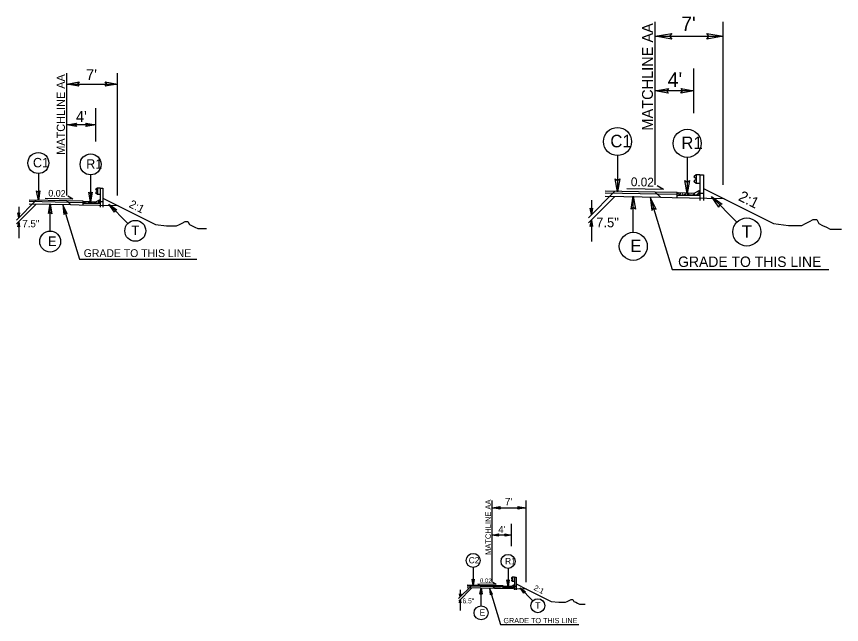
# Model space of a CAD drawing. Extents: x 1818040 to 1825768, y 638918 to 648046.
# Drawn here: x 1818040 to 1819741, y 646793 to 648046 of the extents above; entities that cross this region are included whole.
import ezdxf

# ---------------------------------------------------------------- set-up
doc = ezdxf.new("R2010")
doc.units = 0
for name, color, linetype in [('Old_Level_1', 7, 'Continuous'), ('Prop Dimension', 7, 'Continuous'), ('Prop Dimension Text', 7, 'Continuous'), ('Typical Curb CELL', 7, 'Continuous'), ('Typical Guardrail CELL', 7, 'Continuous'), ('Typical ID Circle CELL', 7, 'Continuous'), ('Typical Pavement Slope CELL', 7, 'Continuous'), ('Typical Pavement Slope Information CELL', 7, 'Continuous'), ('Typical Slope Point Local CELL', 7, 'Continuous'), ('Typical Terminator CELL', 7, 'Continuous'), ('Typical Text General CELL', 7, 'Continuous'), ('Typical Text ID Circle CELL', 7, 'Continuous'), ('Typical Text Label CELL', 7, 'Continuous')]:
    doc.layers.add(name, color=color, linetype=linetype)

msp = doc.modelspace()

# ---------------------------------------------------------------- linework, layer by layer
at = {"layer": 'Old_Level_1'}
for p, q in [((1819273.4, 647685.8), (1819218.9, 647631.3)), ((1819356.8, 647684.1), (1819367.9, 647673)), ((1819447.1, 647687.1), (1819448.8, 647687.9)), ((1818080.9, 647667.2), (1818040.1, 647626.4)), ((1818211.2, 647668.2), (1818212.5, 647668.8)), ((1819273.4, 647674.9), (1819219.2, 647620.8)), ((1819225.1, 647667.3), (1819225.1, 647637.6)), ((1819367.9, 647673), (1819253.6, 647675.3)), ((1819361.1, 647679.8), (1819253.7, 647682)), ((1819346.3, 647673.5), (1819391.8, 647524.4)), ((1819401.8, 647679), (1819361.1, 647679.8)), ((1819391.5, 647672.6), (1819367.9, 647673)), ((1819498.7, 647670.4), (1819391.5, 647672.6)), ((1819401.8, 647672.4), (1819401.8, 647676.9)), ((1818080.9, 647659.1), (1818040.3, 647618.5)), ((1818044.7, 647653.4), (1818044.7, 647631.1)), ((1818151.8, 647657.7), (1818066.1, 647659.4)), ((1818146.7, 647662.8), (1818066.2, 647664.4)), ((1818135.6, 647658), (1818169.8, 647546.2)), ((1818143.5, 647666), (1818151.8, 647657.7)), ((1818177.3, 647662.2), (1818146.7, 647662.8)), ((1818169.5, 647657.3), (1818151.8, 647657.7)), ((1818249.9, 647655.7), (1818169.5, 647657.3)), ((1818177.3, 647657.2), (1818177.3, 647660.6)), ((1818044.7, 647622.9), (1818044.7, 647589.4)), ((1819225.1, 647626.6), (1819225.1, 647582)), ((1818169.8, 647546.2), (1818411.6, 647546.2)), ((1819391.8, 647524.4), (1819714.3, 647524.4)), ((1818978.6, 646874.1), (1818951.4, 646846.9)), ((1818978.6, 646868.7), (1818951.6, 646841.7)), ((1819025.9, 646867.8), (1818968.7, 646868.9)), ((1819022.5, 646871.2), (1818968.8, 646872.3)), ((1819015.1, 646868), (1819037.9, 646793.5)), ((1819020.4, 646873.3), (1819025.9, 646867.8)), ((1819042.9, 646870.8), (1819022.5, 646871.2)), ((1819037.7, 646867.5), (1819025.9, 646867.8)), ((1819091.3, 646866.5), (1819037.7, 646867.5)), ((1819042.9, 646867.4), (1819042.9, 646869.7)), ((1819065.5, 646874.8), (1819066.3, 646875.2)), ((1818954.5, 646864.9), (1818954.5, 646850.1)), ((1818954.5, 646844.6), (1818954.5, 646822.3)), ((1819037.9, 646793.5), (1819199.1, 646793.5))]:
    msp.add_line(p, q, dxfattribs=at)
at = {"layer": 'Prop Dimension'}
for p, q in [((1819356.8, 647699), (1819356.8, 648035)), ((1819496.8, 647699), (1819496.8, 648035)), ((1819356.8, 648005), (1819496.8, 648005)), ((1819436.5, 647847), (1819436.5, 647938.6)), ((1818143.5, 647677.2), (1818143.5, 647929.1)), ((1818248.5, 647677.2), (1818248.5, 647929.1)), ((1818143.5, 647906.6), (1818248.5, 647906.6)), ((1819436.5, 647892.8), (1819356.8, 647892.8)), ((1818203.3, 647788.1), (1818203.3, 647856.9)), ((1818203.3, 647822.5), (1818143.5, 647822.5)), ((1819020.4, 646880.8), (1819020.4, 647048.8)), ((1819090.4, 646880.8), (1819090.4, 647048.8)), ((1819020.4, 647033.8), (1819090.4, 647033.8)), ((1819060.2, 646954.8), (1819060.2, 647000.6)), ((1819060.2, 646977.7), (1819020.4, 646977.7))]:
    msp.add_line(p, q, dxfattribs=at)
at = {"layer": 'Typical Curb CELL'}
for p, q in [((1819401.8, 647683.2), (1819401.8, 647683.2)), ((1819401.8, 647676.9), (1819401.8, 647683)), ((1819402, 647683.2), (1819436.8, 647681.9)), ((1819436.8, 647681.9), (1819447.1, 647687.1)), ((1819447.1, 647676.9), (1819447.1, 647687.1)), ((1818203.5, 647664.3), (1818211.2, 647668.2)), ((1818211.2, 647660.6), (1818211.2, 647668.2)), ((1819447.1, 647676.9), (1819401.8, 647676.9)), ((1819405.4, 647679.2), (1819406.7, 647681)), ((1819407.2, 647679.3), (1819405.4, 647679.2)), ((1819406.7, 647681), (1819407.2, 647679.3)), ((1819416.9, 647678.5), (1819417.8, 647680.2)), ((1819419.3, 647679), (1819416.9, 647678.5)), ((1819417.8, 647680.2), (1819419.3, 647679)), ((1819424.1, 647679.2), (1819425.4, 647681)), ((1819425.9, 647679.3), (1819424.1, 647679.2)), ((1819425.4, 647681), (1819425.9, 647679.3)), ((1819435.6, 647678.5), (1819436.5, 647680.2)), ((1819438.1, 647679), (1819435.6, 647678.5)), ((1819436.5, 647680.2), (1819438.1, 647679)), ((1819444.3, 647682.1), (1819444.5, 647680.7)), ((1819446.6, 647681.4), (1819444.3, 647682.1)), ((1819444.5, 647680.7), (1819446.6, 647681.4)), ((1818177.3, 647665.3), (1818177.3, 647665.3)), ((1818177.3, 647660.6), (1818177.3, 647665.2)), ((1818211.2, 647660.6), (1818177.3, 647660.6)), ((1818177.4, 647665.3), (1818203.5, 647664.3)), ((1818179.9, 647662.3), (1818180.9, 647663.7)), ((1818181.3, 647662.4), (1818179.9, 647662.3)), ((1818180.9, 647663.7), (1818181.3, 647662.4)), ((1818188.5, 647661.7), (1818189.2, 647663)), ((1818190.4, 647662.2), (1818188.5, 647661.7)), ((1818189.2, 647663), (1818190.4, 647662.2)), ((1818194, 647662.3), (1818194.9, 647663.7)), ((1818195.3, 647662.4), (1818194, 647662.3)), ((1818194.9, 647663.7), (1818195.3, 647662.4)), ((1818202.6, 647661.7), (1818203.3, 647663)), ((1818204.4, 647662.2), (1818202.6, 647661.7)), ((1818203.3, 647663), (1818204.4, 647662.2)), ((1818209.1, 647664.5), (1818209.3, 647663.4)), ((1818210.8, 647664), (1818209.1, 647664.5)), ((1818209.3, 647663.4), (1818210.8, 647664)), ((1819042.9, 646872.9), (1819060.4, 646872.2)), ((1819042.9, 646872.9), (1819042.9, 646872.9)), ((1819042.9, 646869.7), (1819042.9, 646872.8)), ((1819065.5, 646869.7), (1819042.9, 646869.7)), ((1819044.6, 646870.9), (1819045.3, 646871.8)), ((1819045.5, 646870.9), (1819044.6, 646870.9)), ((1819045.3, 646871.8), (1819045.5, 646870.9)), ((1819050.4, 646870.5), (1819050.8, 646871.4)), ((1819051.6, 646870.8), (1819050.4, 646870.5)), ((1819050.8, 646871.4), (1819051.6, 646870.8)), ((1819054, 646870.9), (1819054.6, 646871.8)), ((1819054.9, 646870.9), (1819054, 646870.9)), ((1819054.6, 646871.8), (1819054.9, 646870.9)), ((1819059.7, 646870.5), (1819060.2, 646871.4)), ((1819061, 646870.8), (1819059.7, 646870.5)), ((1819060.2, 646871.4), (1819061, 646870.8)), ((1819060.4, 646872.2), (1819065.5, 646874.8)), ((1819064.1, 646872.3), (1819064.2, 646871.6)), ((1819065.2, 646872), (1819064.1, 646872.3)), ((1819064.2, 646871.6), (1819065.2, 646872)), ((1819065.5, 646869.7), (1819065.5, 646874.8))]:
    msp.add_line(p, q, dxfattribs=at)
for centre, radius in [((1819403.2, 647680.5), 0.12), ((1819403.7, 647682.4), 0.12), ((1819409.2, 647681.3), 0.12), ((1819410.1, 647678.6), 0.12), ((1819411, 647678.1), 0.12), ((1819411.5, 647680), 0.12), ((1819412.6, 647680), 0.12), ((1819413.4, 647680.4), 0.12), ((1819414.1, 647678.7), 0.12), ((1819417, 647679.3), 0.12), ((1819420.1, 647679), 0.12), ((1819420.3, 647679.8), 0.12), ((1819420.5, 647680.7), 0.12), ((1819421.3, 647678.5), 0.12), ((1819422.8, 647679.2), 0.12), ((1819424.2, 647679.4), 0.12), ((1819426, 647678.6), 0.12), ((1819428.9, 647678.6), 0.12), ((1819429.7, 647678.1), 0.12), ((1819430.2, 647680), 0.12), ((1819432.1, 647680.4), 0.12), ((1819432.8, 647678.7), 0.12), ((1819435.7, 647679.3), 0.12), ((1819436.1, 647677.8), 0.12), ((1819438.8, 647679), 0.12), ((1819439, 647679.8), 0.12), ((1819442.9, 647679.4), 0.12), ((1819444.7, 647678.6), 0.12), ((1819446.2, 647682.7), 0.12), ((1818178.3, 647663.3), 0.0902), ((1818178.7, 647664.7), 0.0902), ((1818182.8, 647663.9), 0.0902), ((1818183.5, 647661.8), 0.0902), ((1818184.1, 647661.5), 0.0902), ((1818184.5, 647662.9), 0.0902), ((1818185.3, 647662.9), 0.0902), ((1818185.9, 647663.2), 0.0902), ((1818186.4, 647661.9), 0.0902), ((1818188.6, 647662.3), 0.0902), ((1818190.9, 647662.2), 0.0902), ((1818191.1, 647662.7), 0.0902), ((1818191.2, 647663.4), 0.0902), ((1818191.9, 647661.8), 0.0902), ((1818193, 647662.3), 0.0902), ((1818194, 647662.4), 0.0902), ((1818195.4, 647661.8), 0.0902), ((1818197.5, 647661.8), 0.0902), ((1818198.2, 647661.5), 0.0902), ((1818198.5, 647662.9), 0.0902), ((1818200, 647663.2), 0.0902), ((1818200.5, 647661.9), 0.0902), ((1818202.7, 647662.3), 0.0902), ((1818203, 647661.2), 0.0902), ((1818205, 647662.2), 0.0902), ((1818205.2, 647662.7), 0.0902), ((1818208.1, 647662.4), 0.0902), ((1818209.4, 647661.8), 0.0902), ((1818210.5, 647664.9), 0.0902), ((1819043.5, 646871.5), 0.0602), ((1819043.8, 646872.5), 0.0602), ((1819046.6, 646871.9), 0.0602), ((1819047, 646870.6), 0.0602), ((1819047.4, 646870.3), 0.0602), ((1819047.7, 646871.3), 0.0602), ((1819048.2, 646871.3), 0.0602), ((1819048.6, 646871.5), 0.0602), ((1819049, 646870.6), 0.0602), ((1819050.4, 646870.9), 0.0602), ((1819052, 646870.8), 0.0602), ((1819052.1, 646871.2), 0.0602), ((1819052.2, 646871.6), 0.0602), ((1819052.6, 646870.5), 0.0602), ((1819053.3, 646870.9), 0.0602), ((1819054, 646871), 0.0602), ((1819054.9, 646870.6), 0.0602), ((1819056.4, 646870.6), 0.0602), ((1819056.8, 646870.3), 0.0602), ((1819057, 646871.3), 0.0602), ((1819058, 646871.5), 0.0602), ((1819058.3, 646870.6), 0.0602), ((1819059.8, 646870.9), 0.0602), ((1819060, 646870.1), 0.0602), ((1819061.3, 646870.8), 0.0602), ((1819061.5, 646871.2), 0.0602), ((1819063.4, 646871), 0.0602), ((1819064.3, 646870.6), 0.0602), ((1819065, 646872.6), 0.0602)]:
    msp.add_circle(centre, radius, dxfattribs=at)
for centre, radius in [((1819402, 647683), 0.156), ((1818177.4, 647665.2), 0.117), ((1819042.9, 646872.8), 0.0781)]:
    msp.add_arc(centre, radius, 87.952, 180, dxfattribs=at)
at = {"layer": 'Typical Guardrail CELL'}
for p, q in [((1819441.3, 647719.4), (1819437, 647716.4)), ((1819448.8, 647719.4), (1819441.3, 647719.4)), ((1819441.3, 647719.4), (1819441.3, 647702)), ((1819448.8, 647719.4), (1819448.8, 647682.1)), ((1819448.8, 647719.4), (1819456.2, 647719.4)), ((1819456.2, 647719.4), (1819456.2, 647682.1)), ((1819441.3, 647711.4), (1819437, 647714.5)), ((1819441.3, 647710), (1819437, 647707)), ((1819441.3, 647702), (1819437, 647705.1)), ((1819441.3, 647710.7), (1819441.3, 647711.4)), ((1819441.3, 647710.7), (1819441.3, 647710)), ((1819448.8, 647702), (1819441.3, 647702)), ((1818206.9, 647692.5), (1818203.6, 647690.2)), ((1818206.9, 647686.5), (1818203.6, 647688.7)), ((1818206.9, 647685.4), (1818203.6, 647683.1)), ((1818212.5, 647692.5), (1818206.9, 647692.5)), ((1818206.9, 647692.5), (1818206.9, 647679.4)), ((1818206.9, 647685.9), (1818206.9, 647686.5)), ((1818206.9, 647685.9), (1818206.9, 647685.4)), ((1818212.5, 647692.5), (1818212.5, 647664.5)), ((1818212.5, 647692.5), (1818218.1, 647692.5)), ((1818218.1, 647692.5), (1818218.1, 647664.5)), ((1818206.9, 647679.4), (1818203.6, 647681.7)), ((1818212.5, 647679.4), (1818206.9, 647679.4)), ((1819448.8, 647682.1), (1819456.2, 647682.1)), ((1819448.8, 647682.1), (1819448.8, 647667)), ((1819456.2, 647682.1), (1819456.2, 647667)), ((1818212.5, 647664.5), (1818218.1, 647664.5)), ((1818212.5, 647664.5), (1818212.5, 647653.1)), ((1818218.1, 647664.5), (1818218.1, 647653.1)), ((1819062.6, 646891), (1819060.4, 646889.5)), ((1819062.6, 646887), (1819060.4, 646888.5)), ((1819062.6, 646886.3), (1819060.4, 646884.8)), ((1819062.6, 646882.3), (1819060.4, 646883.8)), ((1819066.3, 646891), (1819062.6, 646891)), ((1819062.6, 646891), (1819062.6, 646882.3)), ((1819062.6, 646886.6), (1819062.6, 646887)), ((1819062.6, 646886.6), (1819062.6, 646886.3)), ((1819066.3, 646891), (1819066.3, 646872.3)), ((1819066.3, 646891), (1819070.1, 646891)), ((1819070.1, 646891), (1819070.1, 646872.3)), ((1819066.3, 646882.3), (1819062.6, 646882.3)), ((1819066.3, 646872.3), (1819070.1, 646872.3)), ((1819066.3, 646872.3), (1819066.3, 646864.8)), ((1819070.1, 646872.3), (1819070.1, 646864.8))]:
    msp.add_line(p, q, dxfattribs=at)
for centre, radius, start, end in [((1819437.7, 647715.4), 1.16, 125.003, 235.0112), ((1819437.7, 647706), 1.16, 125.0059, 235.0366), ((1818204.1, 647689.5), 0.874, 125.003, 235.0112), ((1818204.1, 647682.4), 0.874, 125.0059, 235.0366), ((1819060.8, 646889), 0.582, 125.003, 235.0112), ((1819060.8, 646884.3), 0.582, 125.0059, 235.0366)]:
    msp.add_arc(centre, radius, start, end, dxfattribs=at)
at = {"layer": 'Typical ID Circle CELL'}
for p, q in [((1819278.9, 647759.4), (1819278.9, 647684.8)), ((1819422.6, 647755.6), (1819422.6, 647681.1)), ((1818085.1, 647722.4), (1818085.1, 647666.5)), ((1818192.9, 647719.6), (1818192.9, 647663.7)), ((1819311.5, 647601.2), (1819311.5, 647675.8)), ((1819525.2, 647622.3), (1819472.4, 647675)), ((1818109.5, 647603.8), (1818109.5, 647659.7)), ((1818269.8, 647619.6), (1818230.2, 647659.2)), ((1818981.4, 646910.9), (1818981.4, 646873.7)), ((1819053.3, 646909.1), (1819053.3, 646871.8)), ((1818997.7, 646831.9), (1818997.7, 646869.2)), ((1819104.5, 646842.4), (1819078.2, 646868.8))]:
    msp.add_line(p, q, dxfattribs=at)
for centre, radius in [((1819278.9, 647788.2), 28.9), ((1819422.6, 647784.5), 28.9), ((1818085.1, 647744), 21.6), ((1818192.9, 647741.2), 21.6), ((1818285, 647604.3), 21.6), ((1819545.5, 647601.9), 28.9), ((1818109.5, 647582.2), 21.6), ((1819311.5, 647572.4), 28.9), ((1818981.4, 646925.4), 14.4), ((1819053.3, 646923.5), 14.4), ((1819114.7, 646832.2), 14.4), ((1818997.7, 646817.5), 14.4)]:
    msp.add_circle(centre, radius, dxfattribs=at)
at = {"layer": 'Typical Pavement Slope CELL'}
for p, q in [((1819356.8, 647684.1), (1819253.8, 647686.1)), ((1819401.8, 647683.2), (1819356.8, 647684.1)), ((1818143.5, 647666), (1818066.2, 647667.5)), ((1818177.3, 647665.3), (1818143.5, 647666)), ((1819020.4, 646873.3), (1818968.8, 646874.3)), ((1819042.9, 646872.9), (1819020.4, 646873.3))]:
    msp.add_line(p, q, dxfattribs=at)
at = {"layer": 'Typical Pavement Slope Information CELL'}
for p, q in [((1819373.9, 647689.1), (1819297.9, 647690.6)), ((1819373.9, 647689.1), (1819360.4, 647697.2)), ((1818156.3, 647669.7), (1818099.3, 647670.8)), ((1818156.3, 647669.7), (1818146.2, 647675.8)), ((1819028.9, 646875.8), (1818990.9, 646876.6)), ((1819028.9, 646875.8), (1819022.1, 646879.9))]:
    msp.add_line(p, q, dxfattribs=at)
at = {"layer": 'Typical Slope Point Local CELL'}
for p, q in [((1819456.2, 647691.7), (1819498.7, 647670.4)), ((1818218.1, 647671.6), (1818249.9, 647655.7)), ((1819498.7, 647670.4), (1819600.6, 647619.5)), ((1818249.9, 647655.7), (1818326.3, 647617.5)), ((1819070.1, 646877.1), (1819091.3, 646866.5)), ((1819091.3, 646866.5), (1819142.2, 646841))]:
    msp.add_line(p, q, dxfattribs=at)
for points in [[(1818326.3, 647617.5), (1818349.6, 647614.6), (1818355.5, 647614.6), (1818364.2, 647614.6), (1818370.1, 647614.6), (1818375.9, 647617.5), (1818381.8, 647620.4), (1818387.6, 647623.4), (1818393.4, 647623.4), (1818396.4, 647617.5), (1818402.2, 647614.6), (1818408, 647611.7), (1818413.9, 647608.8), (1818419.7, 647608.8), (1818425.5, 647608.8), (1818431.4, 647608.8)], [(1819600.6, 647619.5), (1819631.7, 647615.6), (1819639.5, 647615.6), (1819651.1, 647615.6), (1819658.9, 647615.6), (1819666.7, 647619.5), (1819674.5, 647623.4), (1819682.3, 647627.3), (1819690, 647627.3), (1819693.9, 647619.5), (1819701.7, 647615.6), (1819709.5, 647611.7), (1819717.3, 647607.8), (1819725.1, 647607.8), (1819732.8, 647607.8), (1819740.6, 647607.8)], [(1819142.2, 646841), (1819157.8, 646839.1), (1819161.7, 646839.1), (1819167.5, 646839.1), (1819171.4, 646839.1), (1819175.3, 646841), (1819179.2, 646843), (1819183.1, 646844.9), (1819187, 646844.9), (1819188.9, 646841), (1819192.8, 646839.1), (1819196.7, 646837.1), (1819200.6, 646835.2), (1819204.5, 646835.2), (1819208.4, 646835.2), (1819212.3, 646835.2)]]:
    msp.add_lwpolyline(points, dxfattribs=at)
at = {"layer": 'Typical Terminator CELL'}
for points in [[(1819390.6, 647999.2), (1819356.8, 648005), (1819390.7, 648011), (1819386.4, 648005)], [(1819463.1, 648010.8), (1819496.8, 648005), (1819462.9, 647999), (1819467.2, 648005)], [(1818168.8, 647902.3), (1818143.5, 647906.6), (1818169, 647911.1), (1818165.7, 647906.6)], [(1818223.2, 647911), (1818248.5, 647906.6), (1818223, 647902.1), (1818226.3, 647906.6)], [(1819383.5, 647888.2), (1819356.8, 647892.8), (1819383.7, 647897.6), (1819380.3, 647892.8)], [(1819409.8, 647897.4), (1819436.5, 647892.8), (1819409.6, 647888.1), (1819413, 647892.8)], [(1818163.5, 647819), (1818143.5, 647822.5), (1818163.6, 647826.1), (1818161.1, 647822.5)], [(1818183.2, 647826), (1818203.3, 647822.5), (1818183.1, 647818.9), (1818185.7, 647822.5)], [(1819283.5, 647711.5), (1819278.9, 647684.8), (1819274.2, 647711.7), (1819278.9, 647708.2)], [(1819427.2, 647707.8), (1819422.6, 647681.1), (1819417.9, 647707.9), (1819422.6, 647704.5)], [(1818088.5, 647686.5), (1818085.1, 647666.5), (1818081.5, 647686.6), (1818085.1, 647684.1)], [(1818196.3, 647683.7), (1818192.9, 647663.7), (1818189.3, 647683.8), (1818192.9, 647681.3)], [(1819306.9, 647649.1), (1819311.5, 647675.8), (1819316.3, 647648.9), (1819311.5, 647652.3)], [(1819358.4, 647649.2), (1819346.2, 647673.4), (1819349.5, 647646.3), (1819353, 647651)], [(1819488.1, 647652.9), (1819472.4, 647675), (1819494.8, 647659.4), (1819489, 647658.5)], [(1818106.1, 647639.7), (1818109.5, 647659.7), (1818113.1, 647639.6), (1818109.5, 647642.1)], [(1818144.7, 647639.8), (1818135.6, 647658), (1818138, 647637.6), (1818140.6, 647641.1)], [(1818241.9, 647642.6), (1818230.2, 647659.2), (1818247, 647647.4), (1818242.6, 647646.7)], [(1819227.5, 647651), (1819225.1, 647637.6), (1819222.8, 647651.1), (1819225.2, 647649.3)], [(1818046.5, 647641.1), (1818044.7, 647631.1), (1818043, 647641.2), (1818044.8, 647639.9)], [(1818043, 647612.8), (1818044.7, 647622.9), (1818046.5, 647612.8), (1818044.7, 647614.1)], [(1819222.8, 647613.3), (1819225.1, 647626.6), (1819227.5, 647613.2), (1819225.1, 647614.9)], [(1819037.2, 647030.9), (1819020.4, 647033.8), (1819037.3, 647036.8), (1819035.2, 647033.8)], [(1819073.5, 647036.7), (1819090.4, 647033.8), (1819073.4, 647030.8), (1819075.5, 647033.8)], [(1819033.7, 646975.4), (1819020.4, 646977.7), (1819033.8, 646980.1), (1819032.1, 646977.7)], [(1819046.8, 646980), (1819060.2, 646977.7), (1819046.8, 646975.3), (1819048.5, 646977.7)], [(1818983.7, 646887), (1818981.4, 646873.7), (1818979, 646887.1), (1818981.4, 646885.4)], [(1819055.6, 646885.2), (1819053.3, 646871.8), (1819050.9, 646885.2), (1819053.3, 646883.5)], [(1818995.4, 646855.8), (1818997.7, 646869.2), (1819000.1, 646855.7), (1818997.7, 646857.4)], [(1819021.1, 646855.9), (1819015.1, 646868), (1819016.7, 646854.4), (1819018.5, 646856.8)], [(1819086, 646857.7), (1819078.2, 646868.8), (1819089.3, 646861), (1819086.4, 646860.5)], [(1818955.7, 646856.8), (1818954.5, 646850.1), (1818953.3, 646856.8), (1818954.5, 646855.9)], [(1818953.3, 646837.9), (1818954.5, 646844.6), (1818955.7, 646837.9), (1818954.5, 646838.7)]]:
    msp.add_lwpolyline(points, close=True, dxfattribs=at)

# ---------------------------------------------------------------- texts
at = {"layer": 'Prop Dimension Text'}
for s, height, p in [("7'", 30, (1819410.2, 648015.7)), ("7'", 22.5, (1818183.5, 647914.7)), ("4'", 30, (1819382.3, 647900.7)), ("4'", 22.5, (1818162.6, 647828.4)), ('7.5"', 15, (1818052.1, 647611.6)), ('7.5"', 20, (1819235, 647611.6)), ("7'", 15, (1819047, 647039.1)), ("4'", 15, (1819033.1, 646981.6)), ('6.5"', 10, (1818959.4, 646837.1))]:
    msp.add_text(s, height=height, dxfattribs=at).set_placement(p)
at = {"layer": 'Typical Pavement Slope Information CELL'}
for height, p in [(18.21, (1819306.3, 647696.3)), (13.66, (1818105.6, 647675.1)), (9.11, (1818995.1, 646879.4))]:
    msp.add_text('0.02 ', height=height, rotation=358.8543, dxfattribs=at).set_placement(p)
at = {"layer": 'Typical Text General CELL'}
for height, p in [(16.113, (1818178.7, 647550.3)), (21.484, (1819403.8, 647529.9)), (10.742, (1819043.8, 646796.2))]:
    msp.add_text('GRADE TO THIS LINE', height=height, dxfattribs=at).set_placement(p)
at = {"layer": 'Typical Text ID Circle CELL'}
for s, height, p in [('C1', 25.82, (1819264.1, 647776.3)), ('R1', 25.82, (1819410.5, 647772.6)), ('C1', 19.37, (1818074, 647735.1)), ('R1', 19.37, (1818183.8, 647732.3)), ('T', 25.8, (1819535, 647590)), ('T', 19.4, (1818277.1, 647595.4)), ('E', 19.4, (1818105, 647573.3)), ('E', 25.8, (1819305.4, 647560.5)), ('C2', 12.91, (1818972.2, 646919.4)), ('R1', 12.91, (1819047.2, 646917.6)), ('T', 12.9, (1819109.4, 646826.3)), ('E', 12.9, (1818994.7, 646811.5))]:
    msp.add_text(s, height=height, dxfattribs=at).set_placement(p)
at = {"layer": 'Typical Text Label CELL'}
for s, height, rotation, p in [('MATCHLINE AA', 22.379, 90, (1819351.9, 647810.8)), ('MATCHLINE AA', 16.784, 90, (1818139.8, 647761)), ('2:1', 22.38, 333.4349, (1819526.3, 647668)), ('2:1', 16.78, 333.4349, (1818270.6, 647653.9)), ('MATCHLINE AA', 11.19, 90, (1819017.9, 646936.7)), ('2:1', 11.19, 333.4349, (1819105.1, 646865.3))]:
    msp.add_text(s, height=height, rotation=rotation, dxfattribs=at).set_placement(p)

doc.saveas('drawing.dxf')
